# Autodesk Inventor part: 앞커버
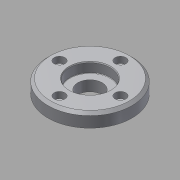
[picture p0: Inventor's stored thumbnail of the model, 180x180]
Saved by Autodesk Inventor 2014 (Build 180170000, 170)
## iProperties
Created: 2015-09
Part Number: 앞커버
Material: 알루미늄 6061
Document SubType Name: Modeling
Designer: mduedu
Density: 1 g/cm^3
Appearance: 알루미늄 - 평지
Author: mduedu
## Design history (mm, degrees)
sketch "스케치1"
  geometry: L1 (0, 7.5)-(0, -7.5); L2 (0, 7.5)-(31, 7.5); L3 (31, 7.5)-(31, -2.5); L4 (31, -2.5)-(17.5, -2.5); L5 (17.5, -2.5)-(17.5, -7.5); L6 (17.5, -7.5)-(0, -7.5); 2 further points
  constraints: 12 end point, 2 parallel, 2 perpendicular, 1 coincident, 1 horizontal, 1 midpoint, 1 vertical
  dimensions: "d0" = 15 distance of L1.start L1.end; "d1" = 62 diameter of L3 L1; "d2" = 35 diameter of L5 L1; "d3" = 10 distance of L2.end L3.end
revolve "회전1" sketch "스케치1" stored, may be unused: angle "d4" = 90 deg
hole "구멍1" diameter "d7" = 30; stored, may be unused: countersink angle "d11" = 90 deg, drill point angle "d13" = 0 deg; dims "d5" = 10, "d6" = 10, "d8" = 6, "d9" = 4, "d10" = 2, "d12" = 7.3
hole "구멍2" diameter "d16" = 18; stored, may be unused: countersink angle "d20" = 90 deg, drill point angle "d22" = 0 deg; dims "d14" = 10, "d15" = 10, "d17" = 6, "d18" = 4, "d19" = 2, "d21" = 7.3
chamfer "모따기1" distance "d23" = 2; stored, may be unused: second distance "d24" = 2, angle "d25" = 45 deg
chamfer "모따기2" distance "d26" = 0.7; stored, may be unused: second distance "d27" = 2, angle "d28" = 30 deg
fillet "모깎기1" dims "d29" = 0.3
sketch "스케치2" dims "d30" = 45
  geometry: 6 further points
  constraints: 2 vertical alignment, 1 coincident, 7 other
  dimensions: "d34" = 360 deg dimension on point (0, 0) point (0, 22.5) (derived)
sketch "스케치3"
  geometry: 4 further points
hole "구멍3" sketch "스케치3" at (0, 22.5), (-22.5, 0), (22.5, 0), (0, -22.5) diameter "d36" = 4.5; stored, may be unused: countersink angle "d40" = 90 deg, drill point angle "d42" = 0 deg; dims "d37" = 6, "d38" = 8, "d39" = 4.6, "d41" = 8
node "솔리드1"
